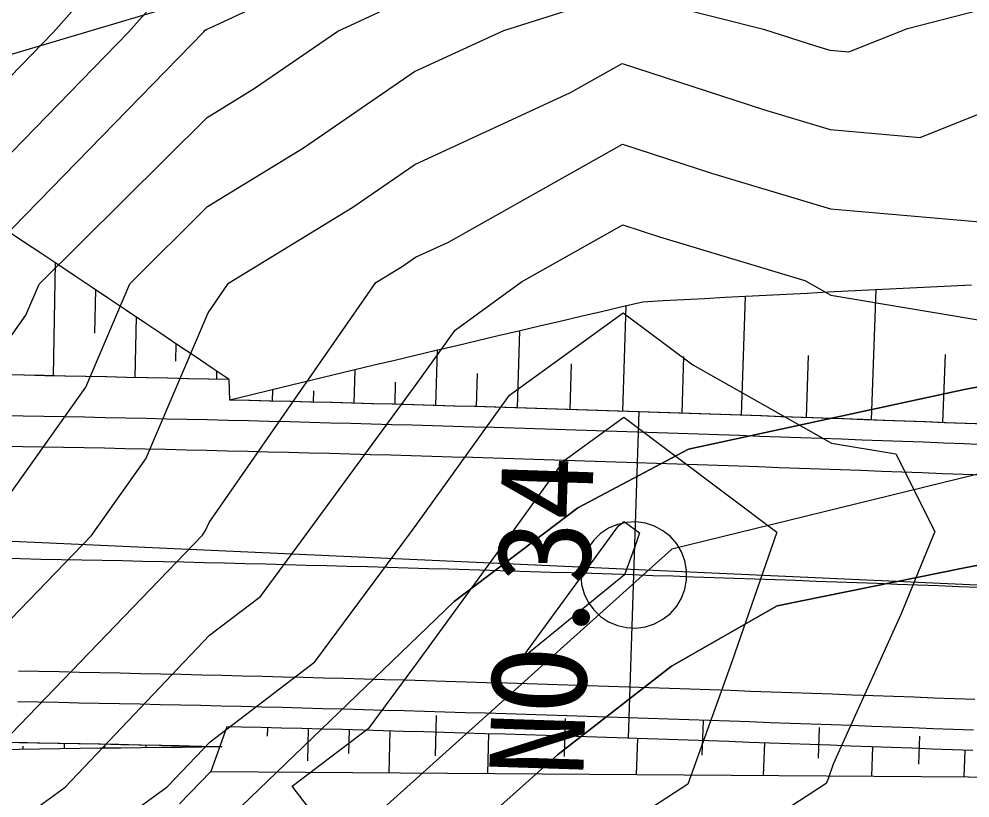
# Model space of a CAD drawing. Extents: x 42655 to 43811, y -141820 to -141156.
# Drawn here: x 43393.3 to 43416.61, y -141344.7 to -141325.62 of the extents above; entities that cross this region are included whole.
import ezdxf

# ---------------------------------------------------------------- set-up
doc = ezdxf.new("R2010")
doc.units = 0
for name, color, linetype in [('D-BMK-HTXT_1', 7, 'Continuous'), ('D-BMK_1', 7, 'Continuous'), ('D-STR', 7, 'Continuous'), ('D-STR-STR4_1', 7, 'Continuous'), ('D-STR-STR5_1', 7, 'Continuous'), ('D-STR_1', 7, 'Continuous'), ('ZE_HICN', 7, 'Continuous'), ('ZE_LWCN', 7, 'Continuous'), ('地形', 7, 'Continuous'), ('現況水路ﾊｯﾁ', 7, 'Continuous'), ('現況道路ﾊｯﾁ', 7, 'Continuous')]:
    doc.layers.add(name, color=color, linetype=linetype)

msp = doc.modelspace()

# ---------------------------------------------------------------- linework, layer by layer
at = {"layer": 'D-BMK-HTXT_1'}
for p, q in [((43439.808, -141340.537), (43274.802, -141333.044)), ((43408.234, -141343.237), (43408.498, -141335.241))]:
    msp.add_line(p, q, dxfattribs=at)
msp.add_lwpolyline([(43407.066, -141339.239), (43407.087, -141339.471), (43407.149, -141339.696), (43407.25, -141339.906), (43407.387, -141340.094), (43407.555, -141340.255), (43407.75, -141340.384), (43407.964, -141340.475), (43408.191, -141340.527), (43408.424, -141340.538), (43408.655, -141340.506), (43408.877, -141340.434), (43409.082, -141340.324), (43409.264, -141340.179), (43409.418, -141340.003), (43409.537, -141339.803), (43409.619, -141339.585), (43409.661, -141339.356), (43409.661, -141339.122), (43409.619, -141338.893), (43409.537, -141338.675), (43409.418, -141338.475), (43409.264, -141338.299), (43409.082, -141338.154), (43408.877, -141338.044), (43408.655, -141337.972), (43408.424, -141337.94), (43408.191, -141337.951), (43407.964, -141338.003), (43407.75, -141338.094), (43407.555, -141338.223), (43407.387, -141338.384), (43407.25, -141338.572), (43407.149, -141338.782), (43407.087, -141339.007), (43407.066, -141339.239)], dxfattribs=at)
at = {"layer": 'D-BMK_1'}
msp.add_lwpolyline([(43416.83, -141339.544), (43416.33, -141339.525), (43415.83, -141339.506), (43415.331, -141339.487), (43414.831, -141339.468), (43414.331, -141339.449), (43413.832, -141339.431), (43413.332, -141339.412), (43412.832, -141339.394), (43412.333, -141339.376), (43411.833, -141339.358), (43411.333, -141339.34), (43410.834, -141339.323), (43410.334, -141339.305), (43409.834, -141339.288), (43409.335, -141339.271), (43408.835, -141339.255), (43408.335, -141339.238), (43407.835, -141339.222), (43407.336, -141339.205), (43406.836, -141339.189), (43406.336, -141339.174), (43405.836, -141339.158), (43405.337, -141339.143), (43404.837, -141339.128), (43404.337, -141339.113), (43403.837, -141339.098), (43403.337, -141339.084), (43402.838, -141339.069), (43402.338, -141339.055), (43401.838, -141339.041), (43401.338, -141339.028), (43400.838, -141339.015), (43400.339, -141339.002), (43399.839, -141338.989), (43399.339, -141338.976), (43398.839, -141338.964), (43398.339, -141338.952), (43397.839, -141338.94), (43397.34, -141338.928), (43396.84, -141338.917), (43396.34, -141338.906), (43395.84, -141338.895), (43395.34, -141338.885), (43394.84, -141338.875), (43394.34, -141338.865), (43393.84, -141338.855), (43393.34, -141338.846), (43392.84, -141338.837)], dxfattribs=at)
at = {"layer": 'D-STR'}
msp.add_line((43397.238, -141344.847), (43398.004, -141344.053), dxfattribs=at)
msp.add_lwpolyline([(43398.004, -141344.053), (43428.165, -141344.263), (43439.578, -141345.606), (43448.093, -141346.151)], dxfattribs=at)
at = {"layer": 'D-STR-STR4_1'}
for p, q in [((43411.003, -141335.326), (43411.105, -141332.418)), ((43414.191, -141335.441), (43414.309, -141332.253)), ((43408.095, -141335.228), (43408.179, -141332.648)), ((43405.515, -141335.146), (43405.572, -141333.258)), ((43403.516, -141335.087), (43403.555, -141333.734)), ((43412.597, -141335.383), (43412.652, -141333.859)), ((43415.938, -141335.507), (43416.002, -141333.836)), ((43406.805, -141335.186), (43406.84, -141334.069)), ((43409.549, -141335.276), (43409.596, -141333.886)), ((43401.516, -141335.031), (43401.538, -141334.214)), ((43404.515, -141335.116), (43404.539, -141334.306)), ((43402.516, -141335.059), (43402.531, -141334.516)), ((43399.517, -141334.979), (43399.524, -141334.698)), ((43400.517, -141335.005), (43400.524, -141334.73)), ((43398.517, -141334.955), (43398.518, -141334.948)), ((43403.528, -141342.682), (43403.499, -141343.668)), ((43398.392, -141342.954), (43398.004, -141344.053)), ((43406.686, -141342.756), (43406.657, -141343.684)), ((43410.065, -141342.814), (43410.036, -141343.654)), ((43399.391, -141342.979), (43399.386, -141343.186)), ((43400.391, -141343.004), (43400.371, -141343.788)), ((43401.391, -141343.031), (43401.375, -141343.608)), ((43402.39, -141343.058), (43402.362, -141344.083)), ((43404.809, -141343.129), (43404.78, -141344.1)), ((43412.91, -141342.97), (43412.882, -141343.728)), ((43415.367, -141343.187), (43415.341, -141343.87)), ((43408.456, -141343.244), (43408.427, -141344.126)), ((43411.566, -141343.351), (43411.538, -141344.147)), ((43414.218, -141343.448), (43414.191, -141344.166)), ((43416.48, -141343.534), (43416.455, -141344.182))]:
    msp.add_line(p, q, dxfattribs=at)
for points in [[(43416.645, -141332.137), (43416.142, -141332.162), (43415.638, -141332.187), (43415.135, -141332.212), (43414.631, -141332.237), (43414.128, -141332.263), (43413.624, -141332.288), (43413.12, -141332.314), (43412.617, -141332.34), (43412.113, -141332.366), (43411.609, -141332.392), (43411.105, -141332.418), (43410.602, -141332.445), (43410.098, -141332.472), (43409.594, -141332.498), (43409.09, -141332.526), (43408.587, -141332.553), (43408.08, -141332.671), (43407.573, -141332.789), (43407.067, -141332.907), (43406.56, -141333.026), (43406.053, -141333.145), (43405.547, -141333.264), (43405.041, -141333.383), (43404.534, -141333.502), (43404.028, -141333.622), (43403.522, -141333.742), (43403.016, -141333.862), (43402.51, -141333.982), (43402.004, -141334.103), (43401.498, -141334.224), (43400.993, -141334.345), (43400.487, -141334.466), (43399.981, -141334.587), (43399.476, -141334.709), (43398.971, -141334.831), (43398.466, -141334.954)], [(43417.015, -141335.548), (43416.515, -141335.529), (43416.014, -141335.51), (43415.513, -141335.491), (43415.012, -141335.472), (43414.511, -141335.453), (43414.01, -141335.434), (43413.509, -141335.416), (43413.008, -141335.398), (43412.507, -141335.38), (43412.006, -141335.362), (43411.505, -141335.344), (43411.004, -141335.326), (43410.503, -141335.309), (43410.002, -141335.292), (43409.5, -141335.275), (43408.999, -141335.258), (43408.498, -141335.241), (43407.997, -141335.225), (43407.495, -141335.208), (43406.994, -141335.192), (43406.492, -141335.177), (43405.991, -141335.161), (43405.49, -141335.146), (43404.988, -141335.13), (43404.486, -141335.115), (43403.985, -141335.101), (43403.483, -141335.086), (43402.982, -141335.072), (43402.48, -141335.058), (43401.978, -141335.044), (43401.477, -141335.03), (43400.975, -141335.017), (43400.473, -141335.004), (43399.971, -141334.991), (43399.469, -141334.978), (43398.967, -141334.966), (43398.466, -141334.954)]]:
    msp.add_lwpolyline(points, dxfattribs=at)
at = {"layer": 'D-STR-STR5_1'}
for p, q in [((43394.192, -141331.595), (43394.139, -141334.361)), ((43395.16, -141333.318), (43395.182, -141332.255)), ((43396.17, -141332.917), (43396.138, -141334.401)), ((43397.147, -141334.001), (43397.157, -141333.579)), ((43398.142, -141334.242), (43398.138, -141334.427)), ((43393.405, -141343.51), (43393.406, -141343.429)), ((43394.408, -141343.367), (43394.405, -141343.496)), ((43395.405, -141343.483), (43395.406, -141343.435)), ((43396.407, -141343.408), (43396.406, -141343.471)), ((43397.406, -141343.46), (43397.407, -141343.445))]:
    msp.add_line(p, q, dxfattribs=at)
for points in [[(43398.456, -141334.454), (43398.037, -141334.171), (43397.617, -141333.889), (43397.198, -141333.606), (43396.778, -141333.324), (43396.358, -141333.043), (43395.938, -141332.761), (43395.517, -141332.479), (43395.096, -141332.198), (43394.676, -141331.917), (43394.254, -141331.636), (43393.833, -141331.356), (43393.412, -141331.075), (43392.99, -141330.795), (43392.568, -141330.515), (43392.146, -141330.236), (43391.723, -141329.956), (43391.3, -141329.677), (43390.877, -141329.398), (43390.454, -141329.119), (43388.503, -141328.092)], [(43398.456, -141334.454), (43397.954, -141334.442), (43397.452, -141334.43), (43396.95, -141334.419), (43396.448, -141334.408), (43395.946, -141334.397), (43395.444, -141334.387), (43394.942, -141334.376), (43394.44, -141334.366), (43393.938, -141334.357), (43393.435, -141334.347), (43392.933, -141334.338)], [(43398.284, -141343.451), (43397.786, -141343.44), (43397.288, -141343.428), (43396.79, -141343.417), (43396.293, -141343.406), (43395.795, -141343.395), (43395.297, -141343.385), (43394.8, -141343.375), (43394.302, -141343.365), (43393.804, -141343.355), (43393.307, -141343.346), (43392.809, -141343.337)], [(43398.284, -141343.451), (43397.786, -141343.456), (43397.288, -141343.461), (43396.79, -141343.467), (43396.292, -141343.472), (43395.794, -141343.478), (43395.297, -141343.484), (43394.799, -141343.491), (43394.301, -141343.497), (43393.803, -141343.504), (43393.306, -141343.512), (43392.808, -141343.519), (43392.31, -141343.527), (43391.813, -141343.535), (43391.315, -141343.544), (43390.818, -141343.553), (43390.321, -141343.562), (43389.823, -141343.571), (43389.326, -141343.581), (43388.828, -141343.591), (43388.331, -141343.601), (43388.316, -141343.602)]]:
    msp.add_lwpolyline(points, dxfattribs=at)
at = {"layer": 'D-STR_1'}
msp.add_line((43398.466, -141334.954), (43398.456, -141334.454), dxfattribs=at)
for points in [[(43398.456, -141334.453), (43398.447, -141334.453), (43397.945, -141334.441), (43397.442, -141334.43), (43396.94, -141334.418), (43396.438, -141334.407), (43395.935, -141334.397), (43395.433, -141334.386), (43394.931, -141334.376), (43394.428, -141334.366), (43393.926, -141334.356), (43393.423, -141334.347), (43392.921, -141334.338)], [(43416.985, -141335.547), (43416.484, -141335.528), (43415.983, -141335.509), (43415.482, -141335.49), (43414.981, -141335.471), (43414.48, -141335.452), (43413.979, -141335.433), (43413.478, -141335.415), (43412.977, -141335.397), (43412.476, -141335.378), (43411.975, -141335.361), (43411.474, -141335.343), (43410.973, -141335.325), (43410.472, -141335.308), (43409.971, -141335.291), (43409.47, -141335.274), (43408.968, -141335.257), (43408.467, -141335.24), (43407.966, -141335.224), (43407.464, -141335.207), (43406.963, -141335.191), (43406.462, -141335.176), (43405.96, -141335.16), (43405.459, -141335.145), (43404.957, -141335.129), (43404.456, -141335.114), (43403.954, -141335.1), (43403.452, -141335.085), (43402.951, -141335.071), (43402.449, -141335.057), (43401.947, -141335.043), (43401.446, -141335.029), (43400.944, -141335.016), (43400.442, -141335.003), (43399.94, -141334.99), (43399.438, -141334.977), (43398.937, -141334.965), (43398.466, -141334.954)], [(43416.965, -141336.047), (43416.465, -141336.027), (43415.964, -141336.008), (43415.463, -141335.989), (43414.962, -141335.97), (43414.462, -141335.952), (43413.961, -141335.933), (43413.46, -141335.915), (43412.959, -141335.896), (43412.458, -141335.878), (43411.958, -141335.86), (43411.457, -141335.843), (43410.956, -141335.825), (43410.455, -141335.808), (43409.954, -141335.79), (43409.453, -141335.773), (43408.952, -141335.757), (43408.45, -141335.74), (43407.949, -141335.723), (43407.448, -141335.707), (43406.947, -141335.691), (43406.446, -141335.675), (43405.945, -141335.66), (43405.443, -141335.644), (43404.942, -141335.629), (43404.441, -141335.614), (43403.939, -141335.599), (43403.438, -141335.585), (43402.937, -141335.571), (43402.435, -141335.557), (43401.934, -141335.543), (43401.432, -141335.529), (43400.931, -141335.516), (43400.429, -141335.503), (43399.928, -141335.49), (43399.426, -141335.477), (43398.924, -141335.465), (43398.423, -141335.453), (43397.921, -141335.441), (43397.419, -141335.429), (43396.918, -141335.418), (43396.416, -141335.407), (43395.914, -141335.396), (43395.412, -141335.386), (43394.91, -141335.376), (43394.408, -141335.366), (43393.907, -141335.356), (43393.405, -141335.347), (43392.903, -141335.338)], [(43416.936, -141336.796), (43416.436, -141336.777), (43415.935, -141336.758), (43415.435, -141336.739), (43414.934, -141336.72), (43414.434, -141336.701), (43413.933, -141336.682), (43413.433, -141336.664), (43412.932, -141336.646), (43412.431, -141336.628), (43411.931, -141336.61), (43411.43, -141336.592), (43410.93, -141336.574), (43410.429, -141336.557), (43409.928, -141336.54), (43409.427, -141336.523), (43408.927, -141336.506), (43408.426, -141336.489), (43407.925, -141336.473), (43407.424, -141336.457), (43406.923, -141336.441), (43406.422, -141336.425), (43405.921, -141336.409), (43405.42, -141336.394), (43404.92, -141336.379), (43404.419, -141336.364), (43403.918, -141336.349), (43403.416, -141336.335), (43402.915, -141336.32), (43402.414, -141336.306), (43401.913, -141336.292), (43401.412, -141336.279), (43400.911, -141336.266), (43400.41, -141336.252), (43399.909, -141336.24), (43399.407, -141336.227), (43398.906, -141336.215), (43398.405, -141336.203), (43397.904, -141336.191), (43397.402, -141336.179), (43396.901, -141336.168), (43396.399, -141336.157), (43395.898, -141336.146), (43395.397, -141336.136), (43394.895, -141336.125), (43394.394, -141336.115), (43393.892, -141336.106), (43393.391, -141336.097), (43392.889, -141336.087)], [(43416.723, -141342.292), (43416.224, -141342.273), (43415.725, -141342.254), (43415.227, -141342.235), (43414.728, -141342.216), (43414.229, -141342.197), (43413.73, -141342.179), (43413.231, -141342.16), (43412.733, -141342.142), (43412.234, -141342.124), (43411.735, -141342.106), (43411.236, -141342.089), (43410.738, -141342.071), (43410.239, -141342.054), (43409.74, -141342.037), (43409.242, -141342.02), (43408.743, -141342.003), (43408.244, -141341.987), (43407.746, -141341.97), (43407.247, -141341.954), (43406.749, -141341.938), (43406.25, -141341.922), (43405.751, -141341.907), (43405.253, -141341.891), (43404.754, -141341.876), (43404.256, -141341.861), (43403.757, -141341.847), (43403.259, -141341.832), (43402.76, -141341.818), (43402.261, -141341.804), (43401.763, -141341.79), (43401.264, -141341.777), (43400.766, -141341.764), (43400.267, -141341.751), (43399.769, -141341.738), (43399.271, -141341.725), (43398.772, -141341.713), (43398.274, -141341.701), (43397.775, -141341.689), (43397.277, -141341.678), (43396.778, -141341.667), (43396.28, -141341.656), (43395.782, -141341.645), (43395.283, -141341.634), (43394.785, -141341.624), (43394.287, -141341.614), (43393.788, -141341.605), (43393.29, -141341.596)], [(43416.694, -141343.041), (43416.195, -141343.022), (43415.697, -141343.003), (43415.198, -141342.984), (43414.7, -141342.965), (43414.201, -141342.947), (43413.702, -141342.928), (43413.204, -141342.91), (43412.705, -141342.892), (43412.207, -141342.874), (43411.709, -141342.856), (43411.21, -141342.838), (43410.712, -141342.821), (43410.213, -141342.803), (43409.715, -141342.786), (43409.216, -141342.769), (43408.718, -141342.753), (43408.22, -141342.736), (43407.721, -141342.72), (43407.223, -141342.704), (43406.725, -141342.688), (43406.226, -141342.672), (43405.728, -141342.656), (43405.23, -141342.641), (43404.732, -141342.626), (43404.233, -141342.611), (43403.735, -141342.596), (43403.237, -141342.582), (43402.739, -141342.568), (43402.241, -141342.554), (43401.742, -141342.54), (43401.244, -141342.527), (43400.746, -141342.513), (43400.248, -141342.5), (43399.75, -141342.488), (43399.252, -141342.475), (43398.754, -141342.463), (43398.256, -141342.451), (43397.758, -141342.439), (43397.26, -141342.428), (43396.762, -141342.416), (43396.264, -141342.405), (43395.766, -141342.395), (43395.268, -141342.384), (43394.77, -141342.374), (43394.272, -141342.364), (43393.774, -141342.355), (43393.276, -141342.345)], [(43416.675, -141343.541), (43416.176, -141343.522), (43415.678, -141343.503), (43415.179, -141343.484), (43414.681, -141343.465), (43414.182, -141343.446), (43413.684, -141343.428), (43413.186, -141343.409), (43412.687, -141343.391), (43412.189, -141343.373), (43411.691, -141343.356), (43411.192, -141343.338), (43410.694, -141343.32), (43410.196, -141343.303), (43409.698, -141343.286), (43409.2, -141343.269), (43408.701, -141343.252), (43408.203, -141343.236), (43407.705, -141343.219), (43407.207, -141343.203), (43406.709, -141343.187), (43406.211, -141343.172), (43405.713, -141343.156), (43405.215, -141343.141), (43404.717, -141343.126), (43404.219, -141343.111), (43403.721, -141343.096), (43403.223, -141343.082), (43402.725, -141343.068), (43402.227, -141343.054), (43401.729, -141343.04), (43401.231, -141343.026), (43400.733, -141343.013), (43400.235, -141343), (43399.737, -141342.987), (43399.239, -141342.975), (43398.742, -141342.963), (43398.392, -141342.954)], [(43398.232, -141343.451), (43397.734, -141343.439), (43397.237, -141343.427), (43396.739, -141343.416), (43396.242, -141343.405), (43395.744, -141343.394), (43395.247, -141343.384), (43394.75, -141343.374), (43394.252, -141343.364), (43393.755, -141343.355), (43393.258, -141343.345)]]:
    msp.add_lwpolyline(points, dxfattribs=at)
at = {"layer": 'ZE_HICN'}
for points in [[(43369.842, -141344.553), (43370.636, -141342.245), (43372.536, -141341.791), (43375.386, -141341.071), (43377.615, -141339.982), (43379.125, -141338.347), (43380.832, -141336.094), (43382.684, -141335.788), (43386.018, -141334.267), (43387.763, -141333.892), (43388.963, -141332.138), (43390.599, -141329.427), (43392.82, -141327.305), (43394.141, -141325.95), (43396.083, -141323.751)], [(43392.883, -141340.551), (43395.076, -141338.271), (43396.406, -141336.393), (43397.934, -141332.814), (43398.436, -141332.093), (43401.482, -141330.228), (43403.005, -141329.183), (43406.82, -141327.422), (43408.082, -141326.714), (43411.547, -141327.84), (43413.177, -141328.329), (43415.384, -141328.521), (43418.261, -141327.37)], [(43405.606, -141341.303), (43407.862, -141338.211), (43407.989, -141338.034), (43408.135, -141337.928), (43408.507, -141338.208), (43408.397, -141338.522), (43408.141, -141339.237), (43405.606, -141341.303)]]:
    msp.add_lwpolyline(points, dxfattribs=at)
at = {"layer": 'ZE_LWCN'}
for points in [[(43368.53, -141351.975), (43372.585, -141352.248), (43373.88, -141350.697), (43374.049, -141346.341), (43377.639, -141344.905), (43377.985, -141344.935), (43378.416, -141344.513), (43382.705, -141340.235), (43383.669, -141339.498), (43387.576, -141338.307), (43387.784, -141338.262), (43391.982, -141332.123), (43392.345, -141331.522), (43392.838, -141331.052), (43397.828, -141325.933), (43397.866, -141325.89), (43397.901, -141325.867), (43397.983, -141325.833), (43402.978, -141323.511)], [(43367.486, -141349.922), (43370.549, -141346.986), (43372.574, -141349.779), (43372.767, -141344.802), (43373.431, -141344.536), (43377.627, -141342.487), (43381.459, -141338.336), (43382.05, -141337.555), (43382.692, -141337.45), (43383.847, -141336.923), (43387.773, -141336.077), (43390.472, -141332.13), (43391.472, -141330.475), (43392.829, -141329.178), (43395.984, -141325.942), (43396.974, -141324.821)], [(43408.073, -141324.989), (43411.549, -141325.868), (43412.822, -141326.281), (43413.168, -141326.385), (43413.637, -141326.426), (43415.074, -141325.852), (43418.25, -141325.026)], [(43367.544, -141362.151), (43371.253, -141361.369), (43371.264, -141356.872), (43371.342, -141355.348), (43372.6, -141355.432), (43376.565, -141350.684), (43376.614, -141349.417), (43377.658, -141349), (43381.654, -141349.335), (43382.743, -141348.269), (43387.813, -141344.468), (43390.102, -141341.087), (43392.426, -141338.284), (43392.868, -141337.559), (43394.939, -141334.634), (43396.02, -141332.104), (43397.922, -141330.216), (43400.273, -141328.777), (43402.994, -141326.909), (43405.184, -141325.898), (43407.488, -141325.177)], [(43369.936, -141353.661), (43372.593, -141353.84), (43375.223, -141350.691), (43375.332, -141347.879), (43377.648, -141346.953), (43379.819, -141347.135), (43382.52, -141344.493), (43382.724, -141344.29), (43385.741, -141341.983), (43387.798, -141341.356), (43388.931, -141339.682), (43390.082, -141338.295), (43392.85, -141333.755), (43393.473, -141332.876), (43393.798, -141332.115), (43397.912, -141328.031), (43399.063, -141327.326), (43401.115, -141325.918), (43402.986, -141325.048)], [(43377.716, -141361.303), (43381.351, -141356.824), (43381.537, -141355.322), (43382.777, -141355.502), (43384.159, -141352.34), (43387.847, -141351.76), (43388.754, -141350.627), (43389.577, -141346.585), (43392.071, -141344.448), (43392.444, -141343.897), (43392.896, -141343.352), (43397.797, -141338.259), (43397.872, -141338.152), (43397.958, -141337.95), (43402.044, -141332.076), (43402.692, -141331.679), (43403.016, -141331.457), (43403.827, -141331.083), (43408.091, -141328.689), (43410.273, -141329.398), (43413.187, -141330.273), (43417.13, -141330.616)], [(43387.9, -141362.822), (43383.733, -141356.813), (43385.162, -141353.544), (43387.854, -141353.12), (43389.853, -141350.621), (43390.46, -141347.644), (43392.906, -141345.547), (43394.43, -141344.437), (43397.971, -141340.712), (43399.216, -141339.764), (43400.339, -141338.247), (43403.031, -141334.57), (43403.992, -141333.238), (43405.616, -141332.059), (43408.1, -141330.665), (43408.999, -141330.956), (43412.559, -141332.026), (43413.197, -141332.386), (43417.396, -141333.083)], [(43392.915, -141347.354), (43396.936, -141344.425), (43397.984, -141343.324), (43400.552, -141341.367), (43402.871, -141338.235), (43403.047, -141337.994), (43405.324, -141334.837), (43408.11, -141332.814), (43409.812, -141334.093), (43413.214, -141336.011), (43414.789, -141336.272), (43415.747, -141338.174), (43414.911, -141340.209), (43413.251, -141343.874), (43413.135, -141344.206), (43413.083, -141344.349), (43408.18, -141347.53)], [(43403.096, -141348.459), (43399.996, -141344.411), (43401.888, -141342.97), (43403.063, -141341.383), (43405.367, -141338.223), (43406.657, -141336.435), (43408.122, -141335.371), (43411.876, -141338.192), (43410.766, -141341.364), (43409.691, -141344.365), (43408.17, -141345.352), (43404.47, -141346.067), (43403.096, -141348.459)]]:
    msp.add_lwpolyline(points, dxfattribs=at)
at = {"layer": '地形'}
for points in [[(43311.115, -141382.224), (43316.422, -141380.309), (43319.224, -141379.204), (43320.361, -141378.505), (43324.721, -141371.676), (43332.93, -141361.58), (43335.811, -141360.459), (43338.506, -141358.906), (43343.589, -141355.977), (43346.837, -141353.684), (43350.07, -141347.302), (43353.317, -141344.706), (43357.132, -141341.056), (43360.297, -141338.947), (43367.215, -141335.453), (43381.438, -141330.388), (43392.065, -141326.794), (43404.164, -141323.199), (43413.973, -141321.075), (43417.897, -141318.951)], [(43420.559, -141333.955), (43416.507, -141334.688), (43409.711, -141336.155), (43406.999, -141337.59), (43403.969, -141339.885), (43396.142, -141347.417), (43393.979, -141349.669), (43390.824, -141352.326), (43385.01, -141356.695), (43381.25, -141360.597), (43377.94, -141364.096), (43375.712, -141366.831), (43374.566, -141369.503), (43371.518, -141375.448), (43367.705, -141378.132)], [(43420.429, -141335.881), (43409.299, -141338.603), (43399.039, -141347.812), (43378.74, -141367.293), (43374.791, -141375.89), (43374.096, -141380.871), (43358.967, -141381.913), (43351.528, -141376.003), (43341.442, -141361.466), (43336.973, -141354.717), (43330.382, -141343.203), (43320.416, -141343.042), (43306.981, -141343.562)], [(43365.816, -141384.557), (43371.007, -141384.046), (43373.48, -141383.978), (43377.671, -141383.154), (43379.113, -141380.546), (43378.014, -141374.986), (43379.67, -141370.33), (43382.279, -141366.72), (43385.49, -141364.163), (43388.46, -141361.966), (43392.84, -141358.986), (43397.221, -141355.039), (43399.085, -141352.463), (43400.703, -141350.134), (43402.568, -141347.75), (43404.25, -141345.648), (43406.494, -141343.647), (43409.29, -141341.474), (43411.879, -141339.99), (43416.471, -141339.059), (43419.923, -141338.403)]]:
    msp.add_lwpolyline(points, dxfattribs=at)
at = {"layer": '現況水路ﾊｯﾁ'}
for points in [[(43367.705, -141378.132), (43371.518, -141375.448), (43374.566, -141369.503), (43375.712, -141366.831), (43377.94, -141364.096), (43381.25, -141360.597), (43385.01, -141356.695), (43390.824, -141352.326), (43393.979, -141349.669), (43396.142, -141347.417), (43403.969, -141339.885), (43406.999, -141337.59), (43409.711, -141336.155), (43416.507, -141334.688), (43420.559, -141333.955)], [(43419.923, -141338.403), (43416.471, -141339.059), (43411.879, -141339.99), (43409.29, -141341.474), (43406.494, -141343.647), (43404.25, -141345.648), (43402.568, -141347.75), (43400.703, -141350.134), (43399.085, -141352.463), (43397.221, -141355.039), (43392.84, -141358.986), (43388.46, -141361.966), (43385.49, -141364.163), (43382.279, -141366.72), (43379.67, -141370.33), (43378.014, -141374.986), (43379.113, -141380.546), (43377.671, -141383.154), (43373.48, -141383.978), (43371.007, -141384.046), (43365.816, -141384.557)]]:
    msp.add_lwpolyline(points, dxfattribs=at)
at = {"layer": '現況道路ﾊｯﾁ'}
msp.add_lwpolyline([(43311.115, -141382.224), (43316.422, -141380.309), (43319.224, -141379.204), (43320.361, -141378.505), (43324.721, -141371.676), (43331.772, -141359.686), (43332.99, -141358.401), (43338.867, -141352.527), (43343.09, -141350.303), (43347.229, -141348.275), (43350.07, -141347.302), (43353.317, -141344.706), (43357.132, -141341.056), (43360.297, -141338.947), (43367.215, -141335.453), (43381.438, -141330.388), (43392.065, -141326.794), (43404.164, -141323.199), (43413.973, -141321.075), (43417.897, -141318.951)], dxfattribs=at)

# ---------------------------------------------------------------- texts
at = {"layer": 'D-BMK-HTXT_1'}
msp.add_text('NO.34', height=2.3065, rotation=88.1084, dxfattribs=at).set_placement((43407.127, -141344.201))

doc.saveas('drawing.dxf')
